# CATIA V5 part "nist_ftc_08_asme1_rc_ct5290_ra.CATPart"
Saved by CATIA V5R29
Part number: NIST PMI FTC 08 ASME1
Revision: C
Description: NIST PMI test model downloaded from http://go.usa.gov/mGVm
Bounding box of the stored display mesh (mm): x -155.797 to 155.797, y -111.347 to 111.347, z 0 to 48.26
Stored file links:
  E:\users\dgn\TPS V5\Import-export annotations\Step\PMI representation 2015\NIST UC\FTC\R29\nist_ftc_08_asme1_ct5240_rc - V5R26 - V2.CATPart
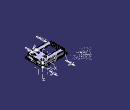
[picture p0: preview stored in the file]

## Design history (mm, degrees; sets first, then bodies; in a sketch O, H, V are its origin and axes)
TTRSSet1
f4a2d38f3ddc11d3a929006094b99c4b_11 "CATTPSSet"
Set1 "MBD_A_GEOM"
  Plane1: type Equation, A 0.57735, B -0.57735, C -0.57735, Length -28.26, RefPoint vertex [face of Fillet7 | start face of Pad1 | face of Pad1 from Sketch5.L4], RefAxis AxisSystem9
Set2
  Point1: type Center, Curve edge [face of Hole1 | start face of Pad1]
  Point2: type OnPlane, Support end face of Pad2, H 142.875, V 98.425, Direction (1, 0, 0)
  Point3: type Center, Curve edge [end face of Pad2 | face of Hole5]
Set3 "MBD_A"
  AxisSystem1 "ABC": origin (142.875, 98.425, 0), X (0, -1, 0), Y (-1, 0, 0), Z (0, 0, -1)
  AxisSystem2 "DBC": origin (142.875, 98.425, 48.26), X (0, 1, 0), Y (-1, 0, 0), Z (0, 0, 1)
Set4 "MBD_B"
  AxisSystem3: origin (142.875, 98.425, 0), X (0, -1, 0), Y (-1, 0, 0), Z (0, 0, -1)
  AxisSystem4: origin (142.875, 98.425, 48.26), X (0, 1, 0), Y (-1, 0, 0), Z (0, 0, 1)
  Sketch1 on face of Pad2 from Sketch6.L3, origin (0, -102.4573, 0), H (1, 0, 0), V (0, 0, 1)
    axis line L1 (0, -16.144) -> (0, 81.9836)
    point P5 (0, -16.144)
    line L2 (50.8, 45.212) -> (50.8, 11.684)
    line L3 (-50.8, 45.212) -> (-50.8, 11.684)
    projected line E4 (121.8957, 11.684) -> (-121.8957, 11.684) from edge [face of Pad2 from Sketch6.L3 | face of Fillet9]
    projected line E5 (50.8, 11.684) -> (-50.8, 11.684) from edge [face of Pad2 from Sketch6.L3 | face of Fillet9]
    distance L1 L2 = 50.8
    distance L1 L3 = 50.8
    coincidence: P5 V
    vertical: L1 V, L2 V, L3 V
  AxisSystem5 "DE-F": origin (-38.1, 0, 48.26), X (0, 1, 0), Y (-1, 0, 0), Z (0, 0, 1)
  Sketch2 on end face of Pad2, origin (0, 0, 48.26), H (1, 0, 0), V (0, 1, 0)
    axis line L1 (-38.1, 55.626) -> (-38.1, -55.626)
    point P1 (-38.1, -55.626)
    point P2 (-38.1, 55.626)
    reference projected point E3 (-38.1, -55.626) from axis of face of RectPattern3
    reference projected point E4 (-38.1, 55.626) from axis of face of RectPattern3
    point P3 (-38.1, 0)
    vertical: L1 V
    coincidence: E3 P1, E4 P2
    midpoint: P3 L1
  Fill1: Boundary Sketch1
Set5 "MBD_C"
  Sketch3 on end face of Pad2, origin (0, 0, 48.26), H (1, 0, 0), V (0, 1, 0)
    axis line L1 (109.22, -20.955) -> (109.22, -78.105)
    point P1 (109.22, -20.955)
    point P2 (109.22, -78.105)
    reference projected point E1 (109.22, -20.955) from axis of face of Hole4
    reference projected point E2 (109.22, -78.105) from axis of face of RectPattern4
    point P3 (109.22, -49.53)
    vertical: L1 V
    coincidence: E1 P1, E2 P2
    midpoint: P3 L1
  AxisSystem6 "DG": origin (109.22, -49.53, 48.26), X (0, 1, 0), Y (-1, 0, 0), Z (0, 0, 1)
  AxisSystem7: origin (142.875, 98.425, 48.26), X (0, 1, 0), Y (-1, 0, 0), Z (0, 0, 1)
Set6 "MBD_D"
  Sketch4 on end face of Pad2, origin (0, 0, 48.26), H (1, 0, 0), V (0, 1, 0)
    axis line L1 (69.85, -25.1263) -> (69.85, -67.31)
    point P2 (69.85, -67.31)
    reference projected point E1 (69.85, -67.31) from axis of face of RectPattern5
    point P3 (69.85, -46.2182)
    vertical: L1 V
    coincidence: E1 P2
    midpoint: P3 L1
  AxisSystem8 "DHJ": origin (69.85, -46.2182, 48.26), X (0, 1, 0), Y (-1, 0, 0), Z (0, 0, 1)
  AxisSystem9 "DKL": origin (69.85, 25.4, 48.26), X (0, 1, 0), Y (-1, 0, 0), Z (0, 0, 1)
  AxisSystem10: origin (142.875, 98.425, 48.26), X (0, 1, 0), Y (-1, 0, 0), Z (0, 0, 1)
Body1 (main body)
  Sketch5 on xy-plane, origin (0, 0, 0), H (1, 0, 0), V (0, 1, 0)
    line L1 (-155.7973, 111.3473) -> (155.7973, 111.3473)
    line L2 (155.7973, 111.3473) -> (155.7973, -111.3473)
    line L3 (155.7973, -111.3473) -> (-155.7973, -111.3473)
    line L4 (-155.7973, -111.3473) -> (-155.7973, 111.3473)
    length L3 = 311.5945
    distance V L4 = 155.7973
    length L2 = 222.6945
    distance H L1 = 111.3473
    horizontal: L1 H, L3 H
    vertical: L2 V, L4 V
  Pad1: profile Sketch5, direction (0, 0, 1), length 10.16
  Sketch6 on end face of Pad1, origin (0, 0, 10.16), H (1, 0, 0), V (0, 1, 0)
    line L1 (-123.1583, 102.4573) -> (123.1583, 102.4573)
    line L2 (146.0183, 79.5973) -> (146.0183, -79.5973)
    line L3 (123.1583, -102.4573) -> (-123.1583, -102.4573)
    line L4 (-146.0183, -79.5973) -> (-146.0183, 79.5973)
    line L5 (123.1583, 102.4573) -> (146.0183, 79.5973)
    line L6 (146.0183, -79.5973) -> (123.1583, -102.4573)
    line L7 (-123.1583, 102.4573) -> (-146.0183, 79.5973)
    point P1 (-142.7555, 82.86)
    line L8 (-146.0183, -79.5973) -> (-123.1583, -102.4573)
    point P2 (-123.1583, 102.4573)
    point P5 (-123.1583, -102.4573)
    point P6 (123.1583, -102.4573)
    point P9 (123.1583, 102.4573)
    reference projected line E1 (-155.7973, 111.3473) -> (-155.7973, -111.3473) from edge [face of Pad1 from Sketch5.L4 | end face of Pad1]
    reference projected line E2 (155.7973, -111.3473) -> (155.7973, 111.3473) from edge [face of Pad1 from Sketch5.L2 | end face of Pad1]
    reference projected line E3 (-155.7973, -111.3473) -> (155.7973, -111.3473) from edge [face of Pad1 from Sketch5.L3 | end face of Pad1]
    reference projected line E4 (155.7973, 111.3473) -> (-155.7973, 111.3473) from edge [face of Pad1 from Sketch5.L1 | end face of Pad1]
    angle L1 L7 = 45
    distance L4 E1 = 9.779
    distance L2 E2 = 9.779
    distance L3 E3 = 8.89
    distance E4 L1 = 8.89
    distance L4 P2 = 22.86
    distance P9 L2 = 22.86
    angle L5 L1 = 45
    distance L2 P6 = 22.86
    angle L3 L6 = 45
    distance P5 L4 = 22.86
    angle L3 L8 = 45
    horizontal: L1 H, L3 H
    vertical: L2 V, L4 V
    coincidence: P1 L7
  Pad2: profile Sketch6, direction (0, 0, 1), length 38.1
  Sketch7 on end face of Pad1, origin (138.8883, 98.2031, 10.16), H (1, 0, 0), V (0, 1, 0)
    point P1 (3.9867, 0.2219)
    reference intersected line E1 through (0, -98.2031) direction (-1, 0) from zx-plane
    reference intersected line E2 through (-138.8883, 0) direction (0, 1) from yz-plane
    distance E1 P1 = 98.425
    distance E2 P1 = 142.875
  Hole1: placed by Sketch7, at (142.875, 98.425, 10.16) direction (0, 0, -1), diameter 6.0325, through (limit type 6)
  RectPattern1: of Hole1, direction 1 instances 2, spacing 285.75, along edge [face of Pad1 from Sketch5.L1 | end face of Pad1], direction 2 instances 2, spacing 196.85, along edge [face of Pad1 from Sketch5.L2 | end face of Pad1] reversed
  Sketch8 on start face of Pad1, origin (0, 0, 0), H (1, 0, 0), V (0, -1, 0)
    line L1 (120.528, 96.1073) -> (139.6683, 76.967)
    line L2 (139.6683, 76.967) -> (139.6683, -76.967)
    line L3 (139.6683, -76.967) -> (120.528, -96.1073)
    line L4 (120.528, -96.1073) -> (-120.528, -96.1073)
    line L5 (-120.528, -96.1073) -> (-139.6683, -76.967)
    line L6 (-139.6683, -76.967) -> (-139.6683, 76.967)
    line L7 (-139.6683, 76.967) -> (-120.528, 96.1073)
    line L8 (-120.528, 96.1073) -> (120.528, 96.1073)
  Pocket1: profile Sketch8, direction (0, 0, 1), length 44.831
  Sketch9 on end face of Pad2, origin (0, 0, 48.26), H (1, 0, 0), V (0, 1, 0)
    point P1 (-107.95, 57.15)
    line L1 (-107.95, 57.15) -> (-90.17, 57.15)
    line L2 (31.75, 57.15) -> (31.75, 33.02)
    line L3 (31.75, -57.15) -> (13.97, -57.15)
    line L4 (-107.95, -57.15) -> (-107.95, -33.02)
    point P3 (31.75, -57.15)
    point P4 (-107.95, -57.15)
    reference intersected line E1 through (0, 0) direction (0, 1) from yz-plane
    reference intersected line E2 through (0, 0) direction (-1, 0) from zx-plane
    arc A1 centre (-106.426, 25.4) radius 7.62 from (-106.426, 17.78) to (-106.426, 33.02) ccw
    point P5 (-106.426, 25.4)
    reference intersected line E3 through (0, 0) direction (-1, 0) from zx-plane
    line L5 (-106.426, 33.02) -> (-107.95, 33.02)
    point P6 (-106.426, 33.02)
    line L6 (-106.426, 17.78) -> (-107.95, 17.78)
    point P7 (-106.426, 17.78)
    point P8 (-107.95, 33.02)
    line L7 (-107.95, 33.02) -> (-107.95, 57.15)
    point P9 (-107.95, 17.78)
    construction line L8 (0, 0) -> (-140, 0)
    point P11 (-107.95, -33.02)
    point P12 (-106.426, -33.02)
    line L9 (-106.426, -33.02) -> (-107.95, -33.02)
    point P13 (-106.426, -17.78)
    arc A2 centre (-106.426, -25.4) radius 7.62 from (-106.426, -17.78) to (-106.426, -33.02) cw
    point P15 (-107.95, -17.78)
    line L10 (-106.426, -17.78) -> (-107.95, -17.78)
    line L11 (-107.95, -17.78) -> (-107.95, 17.78)
    axis line L12 (-38.1, -57.15) -> (-38.1, 57.15)
    point P16 (-38.1, -57.15)
    point P17 (-38.1, 57.15)
    point P18 (30.226, 33.02)
    point P19 (30.226, 17.78)
    arc A3 centre (30.226, 25.4) radius 7.62 from (30.226, 17.78) to (30.226, 33.02) cw
    point P21 (31.75, 17.78)
    line L13 (30.226, 17.78) -> (31.75, 17.78)
    point P22 (31.75, 33.02)
    line L14 (30.226, 33.02) -> (31.75, 33.02)
    point P23 (31.75, -17.78)
    point P24 (30.226, -17.78)
    line L15 (30.226, -17.78) -> (31.75, -17.78)
    point P25 (30.226, -33.02)
    arc A4 centre (30.226, -25.4) radius 7.62 from (30.226, -17.78) to (30.226, -33.02) ccw
    point P27 (31.75, -33.02)
    line L16 (30.226, -33.02) -> (31.75, -33.02)
    line L17 (31.75, 17.78) -> (31.75, -17.78)
    line L18 (31.75, -33.02) -> (31.75, -57.15)
    arc A5 centre (6.35, -55.626) radius 7.62 from (13.97, -55.626) to (-1.27, -55.626) ccw
    point P28 (6.35, -55.626)
    line L19 (13.97, -55.626) -> (13.97, -57.15)
    point P29 (13.97, -55.626)
    line L20 (-1.27, -55.626) -> (-1.27, -57.15)
    point P30 (-1.27, -55.626)
    line L21 (-1.27, -57.15) -> (-30.48, -57.15)
    point P32 (-1.27, -57.15)
    point P33 (-74.93, -57.15)
    point P34 (-74.93, -55.626)
    line L22 (-74.93, -55.626) -> (-74.93, -57.15)
    point P35 (-90.17, -57.15)
    point P36 (-90.17, -55.626)
    line L23 (-90.17, -55.626) -> (-90.17, -57.15)
    arc A6 centre (-82.55, -55.626) radius 7.62 from (-90.17, -55.626) to (-74.93, -55.626) cw
    line L24 (-90.17, -57.15) -> (-107.95, -57.15)
    point P38 (-90.17, 57.15)
    point P39 (-90.17, 55.626)
    line L25 (-90.17, 55.626) -> (-90.17, 57.15)
    point P40 (-74.93, 55.626)
    arc A7 centre (-82.55, 55.626) radius 7.62 from (-90.17, 55.626) to (-74.93, 55.626) ccw
    point P42 (-74.93, 57.15)
    line L26 (-74.93, 55.626) -> (-74.93, 57.15)
    point P43 (-1.27, 57.15)
    point P44 (-1.27, 55.626)
    line L27 (-1.27, 55.626) -> (-1.27, 57.15)
    point P45 (13.97, 55.626)
    arc A8 centre (6.35, 55.626) radius 7.62 from (13.97, 55.626) to (-1.27, 55.626) cw
    line L28 (13.97, 55.626) -> (13.97, 57.15)
    line L29 (13.97, 57.15) -> (31.75, 57.15)
    line L30 (-74.93, 57.15) -> (-45.72, 57.15)
    arc A9 centre (-38.1, -55.626) radius 7.62 from (-30.48, -55.626) to (-45.72, -55.626) ccw
    point P48 (-38.1, -55.626)
    line L31 (-30.48, -55.626) -> (-30.48, -57.15)
    point P49 (-30.48, -55.626)
    line L32 (-45.72, -55.626) -> (-45.72, -57.15)
    point P50 (-45.72, -55.626)
    line L33 (-45.72, -57.15) -> (-74.93, -57.15)
    point P51 (-30.48, -57.15)
    point P52 (-45.72, -57.15)
    point P53 (-45.72, 57.15)
    point P54 (-45.72, 55.626)
    line L34 (-45.72, 55.626) -> (-45.72, 57.15)
    point P55 (-30.48, 55.626)
    arc A10 centre (-38.1, 55.626) radius 7.62 from (-30.48, 55.626) to (-45.72, 55.626) cw
    point P57 (-30.48, 57.15)
    line L35 (-30.48, 55.626) -> (-30.48, 57.15)
    line L36 (-30.48, 57.15) -> (-1.27, 57.15)
    distance L4 E1 = 107.95
    distance E2 L3 = 57.15
    distance P5 L4 = 1.524
    radius A1 = 7.62
    distance E3 P5 = 25.4
    distance P4 P1 = 114.3
    radius A5 = 7.62
    distance L3 P28 = 1.524
    distance P28 L12 = 44.45
    distance P3 P4 = 139.7
    radius A9 = 7.62
    distance L21 P48 = 1.524
    horizontal: L1 H, L3 H, L5 H, L6 H, L8 H, L21 H, L24 H, L29 H, L30 H, L33 H, L36 H
    vertical: L2 V, L4 V, L7 V, L11 V, L12 V, L17 V, L18 V, L20 V, L19 V, L31 V, L32 V
    tangency: L5 A1, L6 A1, L19 A5, L20 A5, L31 A9, L32 A9
    coincidence: L4 P8, L4 L11, L2 L17, L17 L18, L3 P16, L3 L21, L1 P17, L1 L29, P48 L12, L21 L33, L30 L36
    symmetry: P8 P11 L8, P6 P12 L8, L5 L9 L8, P7 P13 L8, A1 A2 L8, P9 P15 L8, L6 L10 L8, P6 P18 L12, P7 P19 L12, A1 A3 L12, P9 P21 L12, L6 L13 L12, P8 P22 L12, L5 L14 L12, P15 P23 L12, P13 P24 L12, L10 L15 L12, P12 P25 L12, A2 A4 L12, P11 P27 L12, L9 L16 L12, P32 P33 L12, P30 P34 L12, L20 L22 L12, P29 P36 L12, L19 L23 L12, A5 A6 L12, P35 P38 L8, P36 P39 L8, L23 L25 L8, P34 P40 L8, A6 A7 L8, P33 P42 L8, L22 L26 L8, P32 P43 L8, P30 P44 L8, L20 L27 L8, P29 P45 L8, A5 A8 L8, L19 L28 L8, P52 P53 L8, P50 P54 L8, L32 L34 L8, P49 P55 L8, A9 A10 L8, P51 P57 L8, L31 L35 L8
  Pocket2: profile Sketch9, direction (0, 0, -1), through (limit type 6)
  Sketch10 on end face of Pad2, origin (-103.9484, 24.3967, 48.26), H (1, 0, 0), V (0, 1, 0)
    point P1 (-2.4776, 1.0033)
    reference projected arc E1 centre (-2.4776, 1.0033) radius 7.62 from (-2.4776, -6.6167) to (-2.4776, 8.6233) ccw from edge [end face of Pad2 | face of Pocket2 from Sketch9.A1]
    concentricity: E1 P1
  Hole2: placed by Sketch10, at (-106.426, 25.4, 48.26) direction (0, 0, -1), diameter 5.4102, through (limit type 6)
  RectPattern2: of Hole2, direction 1 instances 2, spacing 50.8, along edge [end face of Pad2 | face of Pocket2 from Sketch9.L11], direction 2 instances 2, spacing 136.652, along edge [end face of Pad2 | face of Pocket2 from Sketch9.L21]
  Sketch11 on end face of Pad2, origin (-83.348, -53.7047, 48.26), H (1, 0, 0), V (0, 1, 0)
    point P1 (0.798, -1.9213)
    reference projected point E1 (0.798, -1.9213) from axis of face of Pocket2 from Sketch9.A6
    coincidence: E1 P1
  Hole3: placed by Sketch11, at (-82.55, -55.626, 48.26) direction (0, 0, -1), diameter 5.4102, through (limit type 6)
  RectPattern3: of Hole3, direction 1 instances 3, spacing 44.45, along edge [end face of Pad2 | face of Pocket2 from Sketch9.L33], direction 2 instances 2, spacing 111.252, along edge [end face of Pad2 | face of Pocket2 from Sketch9.L11] reversed
  Sketch12 on end face of Pad2, origin (0, 0, 48.26), H (1, 0, 0), V (0, 1, 0)
    line L1 (95.25, -35.56) -> (123.19, -35.56)
    line L2 (123.19, -35.56) -> (123.19, -63.5)
    line L3 (123.19, -63.5) -> (95.25, -63.5)
    line L4 (95.25, -63.5) -> (95.25, -35.56)
    reference intersected line E1 through (0, 0) direction (0, 1) from yz-plane
    reference intersected line E2 through (0, 0) direction (-1, 0) from zx-plane
    length L1 = 27.94
    length L2 = 27.94
    distance E1 L4 = 95.25
    distance E2 L1 = 35.56
    horizontal: L1 H, L3 H
    vertical: L2 V, L4 V
  Pocket3: profile Sketch12, direction (0, 0, -1), through (limit type 6)
  Sketch13 on end face of Pad2, origin (108.1397, -22.5136, 48.26), H (1, 0, 0), V (0, 1, 0)
    point P1 (1.0803, 1.5586)
    reference intersected line E1 through (-108.1397, 0) direction (0, 1) from yz-plane
    reference intersected line E2 through (0, 22.5136) direction (-1, 0) from zx-plane
    distance E1 P1 = 109.22
    distance E2 P1 = 20.955
  Hole4: placed by Sketch13, at (109.22, -20.955, 48.26) direction (0, 0, -1), diameter 6.35, through (limit type 6)
  RectPattern4: of Hole4, direction 1 instances 2, spacing 57.15, along edge [end face of Pad2 | face of Pocket3 from Sketch12.L2] reversed, direction 2 instances 2, spacing 111.252
  Sketch14 on end face of Pad2, origin (96.9796, 25.3434, 48.26), H (1, 0, 0), V (0, 1, 0)
    point P1 (-27.1296, 0.0566)
    reference intersected line E1 through (-96.9796, 0) direction (0, 1) from yz-plane
    reference intersected line E2 through (0, -25.3434) direction (-1, 0) from zx-plane
    distance E1 P1 = 69.85
    distance P1 E2 = 25.4
  Hole5: placed by Sketch14, at (69.85, 25.4, 48.26) direction (0, 0, -1), diameter 5.7912, through (limit type 6)
  RectPattern5: of Hole5, direction 1 instances 2, spacing 92.71, along edge [face of Pad2 from Sketch6.L2 | end face of Pad2] reversed, direction 2 instances 2, spacing 111.252
  Sketch15 on end face of Pad2, origin (70.1334, 59.5545, 48.26), H (1, 0, 0), V (0, 1, 0)
    point P1 (-0.2834, 7.7555)
    reference intersected line E1 through (0, -59.5545) direction (-1, 0) from zx-plane
    reference intersected line E2 through (-70.1334, 0) direction (0, 1) from yz-plane
    distance E1 P1 = 67.31
    distance E2 P1 = 69.85
  Hole6: placed by Sketch15, at (69.85, 67.31, 48.26) direction (0, 0, -1), diameter 6.1468, through (limit type 6)
  RectPattern6: of Hole6, direction 1 instances 2, spacing 92.71, along edge [face of Pad2 from Sketch6.L2 | end face of Pad2] reversed, direction 2 instances 2, spacing 111.252
  Sketch16 on end face of Pad2, origin (0, 0, 48.26), H (1, 0, 0), V (0, 1, 0)
    construction line L1 (50, 46.355) -> (180, 46.355)
    construction line L2 (59.69, 70) -> (59.69, -80)
    reference intersected line E1 through (0, 0) direction (0, 1) from yz-plane
    reference intersected line E2 through (0, 0) direction (-1, 0) from zx-plane
    arc A1 centre (59.69, 54.61) radius 7.62 from (67.31, 54.61) to (52.07, 54.61) ccw
    point P5 (59.69, 54.61)
    arc A2 centre (59.69, 38.1) radius 7.62 from (67.31, 38.1) to (52.07, 38.1) cw
    line L3 (46.99, 52.705) -> (46.99, 40.005)
    line L4 (46.99, 52.705) -> (52.07, 52.705)
    point P7 (46.99, 52.705)
    line L5 (52.07, 54.61) -> (52.07, 52.705)
    line L6 (67.31, 54.61) -> (67.31, 51.435)
    point P8 (67.31, 54.61)
    point P9 (67.31, 38.1)
    arc A3 centre (67.31, 46.355) radius 5.08 from (67.31, 41.275) to (67.31, 51.435) ccw
    point P10 (67.31, 46.355)
    line L7 (67.31, 41.275) -> (67.31, 38.1)
    point P12 (52.312, 52.705)
    point P13 (67.31, 54.61)
    line L8 (46.99, 40.005) -> (52.07, 40.005)
    line L9 (52.07, 38.1) -> (52.07, 40.005)
    axis line L10 (-21.2756, -46.355) -> (171.7584, -46.355)
    reference intersected line E3 through (0, 0) direction (-1, 0) from zx-plane
    arc A4 centre (59.69, -38.1) radius 7.62 from (67.31, -38.1) to (52.07, -38.1) ccw
    point P24 (59.69, -38.1)
    arc A5 centre (59.69, -54.61) radius 7.62 from (52.07, -54.61) to (67.31, -54.61) ccw
    point P25 (59.69, -54.61)
    point P26 (67.31, -54.61)
    arc A6 centre (67.31, -46.355) radius 5.08 from (67.31, -51.435) to (67.31, -41.275) ccw
    point P27 (67.31, -46.355)
    line L11 (67.31, -38.1) -> (67.31, -41.275)
    point P28 (67.31, -38.1)
    line L12 (67.31, -54.61) -> (67.31, -51.435)
    line L13 (52.07, -38.1) -> (52.07, -54.61)
    distance E1 L2 = 59.69
    distance E2 L1 = 46.355
    radius A1 = 7.62
    distance P5 L1 = 8.255
    distance L3 L2 = 12.7
    distance L1 L4 = 6.35
    radius A3 = 5.08
    distance E3 L10 = 46.355
    distance P24 P25 = 16.51
    distance L10 P24 = 8.255
    radius A6 = 5.08
    horizontal: L1 H, L4 H, L10 H
    vertical: L2 V, L3 V, L6 V, L7 V, L5 V, L9 V, L11 V
    coincidence: P5 L2, P7 L3, P8 A1, P9 A2, L6 P10, L6 L7, A1 P12, L6 P13, P12 L4, P24 L2, P25 L2, A5 P26, P26 L6, P27 L10, P28 A4, P27 L11
    symmetry: A1 A2 L1, L4 L8 L1
    tangency: L5 A1, L9 A2, L6 A1, A4 L6, A5 L6, L11 A4, L12 A5, L13 A5
    equidistance: P8 P9 P10
  Pocket4: profile Sketch16, direction (0, 0, -1), through (limit type 6)
  Sketch17 on end face of Pad2, origin (0, 0, 48.26), H (1, 0, 0), V (0, 1, 0)
    line L1 (-130.81, 79.375) -> (-118.11, 79.375)
    line L2 (-118.11, 79.375) -> (-118.11, -79.375)
    line L3 (-118.11, -79.375) -> (-130.81, -79.375)
    line L4 (-130.81, -79.375) -> (-130.81, 79.375)
    reference intersected line E1 through (0, 0) direction (-1, 0) from zx-plane
    reference intersected line E2 through (0, 0) direction (0, 1) from yz-plane
    length L1 = 12.7
    distance E1 L1 = 79.375
    length L4 = 158.75
    distance E2 L2 = 118.11
    horizontal: L1 H, L3 H
    vertical: L2 V, L4 V
  Pocket5: profile Sketch17, direction (0, 0, -1), length 1.27
  Fillet1: radius 3.175, on edge [face of Pocket2 from Sketch9.L24 | face of Pocket2 from Sketch9.L4]; edge [face of Pocket2 from Sketch9.L4 | face of Pocket2 from Sketch9.L9]; edge [face of Pocket2 from Sketch9.L10 | face of Pocket2 from Sketch9.L11]; edge [face of Pocket2 from Sketch9.L11 | face of Pocket2 from Sketch9.L6]; edge [face of Pocket2 from Sketch9.L5 | face of Pocket2 from Sketch9.L7]; edge [face of Pocket2 from Sketch9.L7 | face of Pocket2 from Sketch9.L1]; edge [face of Pocket2 from Sketch9.L1 | face of Pocket2 from Sketch9.L25]; edge [face of Pocket2 from Sketch9.L26 | face of Pocket2 from Sketch9.L30]; edge [face of Pocket2 from Sketch9.L30 | face of Pocket2 from Sketch9.L34]; edge [face of Pocket2 from Sketch9.L35 | face of Pocket2 from Sketch9.L36]; edge [face of Pocket2 from Sketch9.L36 | face of Pocket2 from Sketch9.L27]; edge [face of Pocket2 from Sketch9.L28 | face of Pocket2 from Sketch9.L29]; edge [face of Pocket2 from Sketch9.L29 | face of Pocket2 from Sketch9.L2]; edge [face of Pocket2 from Sketch9.L2 | face of Pocket2 from Sketch9.L14]; edge [face of Pocket2 from Sketch9.L13 | face of Pocket2 from Sketch9.L17]; edge [face of Pocket2 from Sketch9.L17 | face of Pocket2 from Sketch9.L15]; edge [face of Pocket2 from Sketch9.L16 | face of Pocket2 from Sketch9.L18]; edge [face of Pocket2 from Sketch9.L18 | face of Pocket2 from Sketch9.L3]; edge [face of Pocket2 from Sketch9.L3 | face of Pocket2 from Sketch9.L19]; edge [face of Pocket2 from Sketch9.L20 | face of Pocket2 from Sketch9.L21]; edge [face of Pocket2 from Sketch9.L21 | face of Pocket2 from Sketch9.L31]; edge [face of Pocket2 from Sketch9.L32 | face of Pocket2 from Sketch9.L33]; edge [face of Pocket2 from Sketch9.L33 | face of Pocket2 from Sketch9.L22]; edge [face of Pocket2 from Sketch9.L23 | face of Pocket2 from Sketch9.L24]
  Fillet2: radius 3.175, on edge [face of Pocket5 from Sketch17.L3 | face of Pocket5 from Sketch17.L4]; edge [face of Pocket5 from Sketch17.L2 | face of Pocket5 from Sketch17.L3]; edge [face of Pocket5 from Sketch17.L4 | face of Pocket5 from Sketch17.L1]; edge [face of Pocket5 from Sketch17.L1 | face of Pocket5 from Sketch17.L2]
  Fillet3: radius 0.762, on edge [face of Pocket5 from Sketch17.L4 | end face of Pocket5]
  Fillet4: radius 1.5875, on edge [face of Pocket4 from Sketch16.L8 | face of Pocket4 from Sketch16.L3]; edge [face of Pocket4 from Sketch16.L3 | face of Pocket4 from Sketch16.L4]
  Fillet5: radius 1.5875, on edge [face of Pocket3 from Sketch12.L3 | face of Pocket3 from Sketch12.L4]; edge [face of Pocket3 from Sketch12.L4 | face of Pocket3 from Sketch12.L1]; edge [face of Pocket3 from Sketch12.L1 | face of Pocket3 from Sketch12.L2]; edge [face of Pocket3 from Sketch12.L2 | face of Pocket3 from Sketch12.L3]
  Fillet6: radius 3.048, on edge [face of Pad2 from Sketch6.L4 | face of Pad2 from Sketch6.L7]; edge [face of Pad2 from Sketch6.L7 | end face of Pad2]; edge [face of Pad2 from Sketch6.L4 | end face of Pad2]; edge [face of Pad2 from Sketch6.L8 | face of Pad2 from Sketch6.L4]; edge [face of Pad2 from Sketch6.L8 | end face of Pad2]; edge [face of Pad2 from Sketch6.L3 | face of Pad2 from Sketch6.L8]; edge [face of Pad2 from Sketch6.L3 | end face of Pad2]; edge [face of Pad2 from Sketch6.L6 | face of Pad2 from Sketch6.L3]; edge [face of Pad2 from Sketch6.L6 | end face of Pad2]; edge [face of Pad2 from Sketch6.L2 | face of Pad2 from Sketch6.L6]; edge [face of Pad2 from Sketch6.L2 | end face of Pad2]; edge [face of Pad2 from Sketch6.L5 | face of Pad2 from Sketch6.L2]; edge [face of Pad2 from Sketch6.L5 | end face of Pad2]; edge [face of Pad2 from Sketch6.L1 | face of Pad2 from Sketch6.L5]; edge [face of Pad2 from Sketch6.L1 | end face of Pad2]; edge [face of Pad2 from Sketch6.L7 | face of Pad2 from Sketch6.L1]
  Fillet7: radius 3.048, on edge [face of Pad1 from Sketch5.L1 | face of Pad1 from Sketch5.L2]; edge [face of Pad1 from Sketch5.L1 | end face of Pad1]; edge [face of Pad1 from Sketch5.L2 | end face of Pad1]; edge [face of Pad1 from Sketch5.L4 | face of Pad1 from Sketch5.L1]; edge [face of Pad1 from Sketch5.L4 | end face of Pad1]; edge [face of Pad1 from Sketch5.L3 | face of Pad1 from Sketch5.L4]; edge [face of Pad1 from Sketch5.L3 | end face of Pad1]; edge [face of Pad1 from Sketch5.L2 | face of Pad1 from Sketch5.L3]
  Fillet8: radius 3.048, on edge [face of Pocket1 from Sketch8.L8 | face of Pocket1 from Sketch8.L1]; edge [face of Pocket1 from Sketch8.L8 | end face of Pocket1]; edge [face of Pocket1 from Sketch8.L1 | end face of Pocket1]; edge [face of Pocket1 from Sketch8.L7 | face of Pocket1 from Sketch8.L8]; edge [face of Pocket1 from Sketch8.L7 | end face of Pocket1]; edge [face of Pocket1 from Sketch8.L6 | face of Pocket1 from Sketch8.L7]; edge [face of Pocket1 from Sketch8.L6 | end face of Pocket1]; edge [face of Pocket1 from Sketch8.L5 | face of Pocket1 from Sketch8.L6]; edge [face of Pocket1 from Sketch8.L5 | end face of Pocket1]; edge [face of Pocket1 from Sketch8.L4 | face of Pocket1 from Sketch8.L5]; edge [face of Pocket1 from Sketch8.L4 | end face of Pocket1]; edge [face of Pocket1 from Sketch8.L3 | end face of Pocket1]; edge [face of Pocket1 from Sketch8.L3 | face of Pocket1 from Sketch8.L4]; edge [face of Pocket1 from Sketch8.L2 | end face of Pocket1]; edge [face of Pocket1 from Sketch8.L2 | face of Pocket1 from Sketch8.L3]; edge [face of Pocket1 from Sketch8.L1 | face of Pocket1 from Sketch8.L2]
  Sketch18 on end face of Pad2, origin (103.8066, 57.5041, 48.26), H (1, 0, 0), V (0, 1, 0)
    point P1 (7.9534, 5.9959)
    reference intersected line E1 through (0, -57.5041) direction (-1, 0) from zx-plane
    reference intersected line E2 through (-103.8066, 0) direction (0, 1) from yz-plane
    distance E1 P1 = 63.5
    distance E2 P1 = 111.76
  Hole7: placed by Sketch18, at (111.76, 63.5, 48.26) direction (0, 0, -1), diameter 30.5587, through (limit type 6)
  Sketch19 on end face of Pad2, origin (92.1729, 62.3356, 48.26), H (1, 0, 0), V (0, 1, 0)
    point P1 (5.2996, 1.1644)
    reference intersected line E1 through (0, -62.3356) direction (-1, 0) from zx-plane
    reference intersected line E2 through (-92.1729, 0) direction (0, 1) from yz-plane
    distance E1 P1 = 63.5
    distance E2 P1 = 97.4725
  Hole8: placed by Sketch19, at (97.4725, 63.5, 48.26) direction (0, 0, -1), diameter 6.35, through (limit type 6)
  Sketch20 on end face of Pad2, origin (0, 0, 48.26), H (1, 0, 0), V (0, 1, 0)
    axis line L1 (-38.1, 55.626) -> (-38.1, -55.626)
    point P1 (-38.1, -55.626)
    point P2 (-38.1, 55.626)
    reference projected point E3 (-38.1, -55.626) from axis of face of RectPattern3
    reference projected point E4 (-38.1, 55.626) from axis of face of RectPattern3
    point P3 (-38.1, 0)
    vertical: L1 V
    coincidence: E3 P1, E4 P2
    midpoint: P3 L1
  Fillet9: radius 1.524, on edge [end face of Pad1 | face of Pad2 from Sketch6.L3]
  Sketch21 "Main View" on face of Pad2 from Sketch6.L2, origin (146.0183, 0, 0), H (0, 1, 0), V (0, 0, 1)
    line L1 (-6.1589, 40.4) -> (-6.1589, 29.5957)
    arc A1 centre (-1.9632, 29.5957) radius 4.1957 from (-6.1589, 29.5957) to (-1.9632, 25.4) ccw
    line L2 (-1.9632, 25.4) -> (13.2373, 25.4)
    arc A2 centre (12.5189, 29.9115) radius 4.5683 from (13.2373, 25.4) to (13.2373, 34.4229) ccw
    line L3 (13.2373, 34.4229) -> (3.6106, 34.4229)
    arc A3 centre (3.6106, 35.8333) radius 1.4104 from (3.7255, 37.239) to (3.6106, 34.4229) ccw
    line L4 (3.7255, 37.239) -> (19.4156, 37.239)
    line L5 (19.4156, 37.239) -> (19.4156, 25.4)
    line L6 (19.4156, 25.4) -> (22.5181, 25.4)
    line L7 (22.5181, 25.4) -> (22.5181, 37.239)
    line L8 (22.5181, 37.239) -> (28.9274, 37.239)
    line L9 (28.9274, 37.239) -> (28.9274, 40.4)
    line L10 (28.9274, 40.4) -> (3.3241, 40.4)
    arc A4 centre (3.3241, 35.8533) radius 4.5467 from (3.3241, 40.4) to (3.6681, 31.3196) ccw
    line L11 (3.6681, 31.3196) -> (12.7199, 31.3196)
    arc A5 centre (12.5972, 29.9083) radius 1.4166 from (12.7774, 28.5032) to (12.7199, 31.3196) ccw
    line L12 (12.7774, 28.5032) -> (-1.9341, 28.5032)
    line L13 (-3.0266, 29.5957) -> (-3.0266, 40.4)
    line L14 (-3.0266, 40.4) -> (-6.1589, 40.4)
    line L15 (-27.94, 25.4) -> (-27.94, 37.5621)
    arc A6 centre (-24.679, 37.5621) radius 3.261 from (-22.2848, 39.7761) to (-27.94, 37.5621) ccw
    line L16 (-22.2848, 39.7761) -> (-12.02, 28.6757)
    arc A7 centre (-11.7155, 28.9572) radius 0.4146 from (-12.02, 28.6757) to (-11.3023, 28.9919) ccw
    line L17 (-11.3023, 28.9919) -> (-11.3023, 40.4)
    line L18 (-11.3023, 40.4) -> (-8.1701, 40.4)
    line L19 (-8.1701, 40.4) -> (-8.1701, 28.9171)
    line L20 (-14.4332, 26.7194) -> (-23.9003, 37.009)
    arc A8 centre (-24.2976, 36.6435) radius 0.5399 from (-23.9003, 37.009) to (-24.8375, 36.6435) ccw
    line L21 (-24.8375, 36.6435) -> (-24.8375, 25.4)
    line L22 (-24.8375, 25.4) -> (-27.94, 25.4)
    arc A9 centre (-1.9341, 29.5957) radius 1.0926 from (-3.0266, 29.5957) to (-1.9341, 28.5032) ccw
    arc A10 centre (-11.6872, 28.9171) radius 3.5171 from (-14.4332, 26.7194) to (-8.1701, 28.9171) ccw
  Pocket6: profile Sketch21, direction (-1, 0, 0), length 2.54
